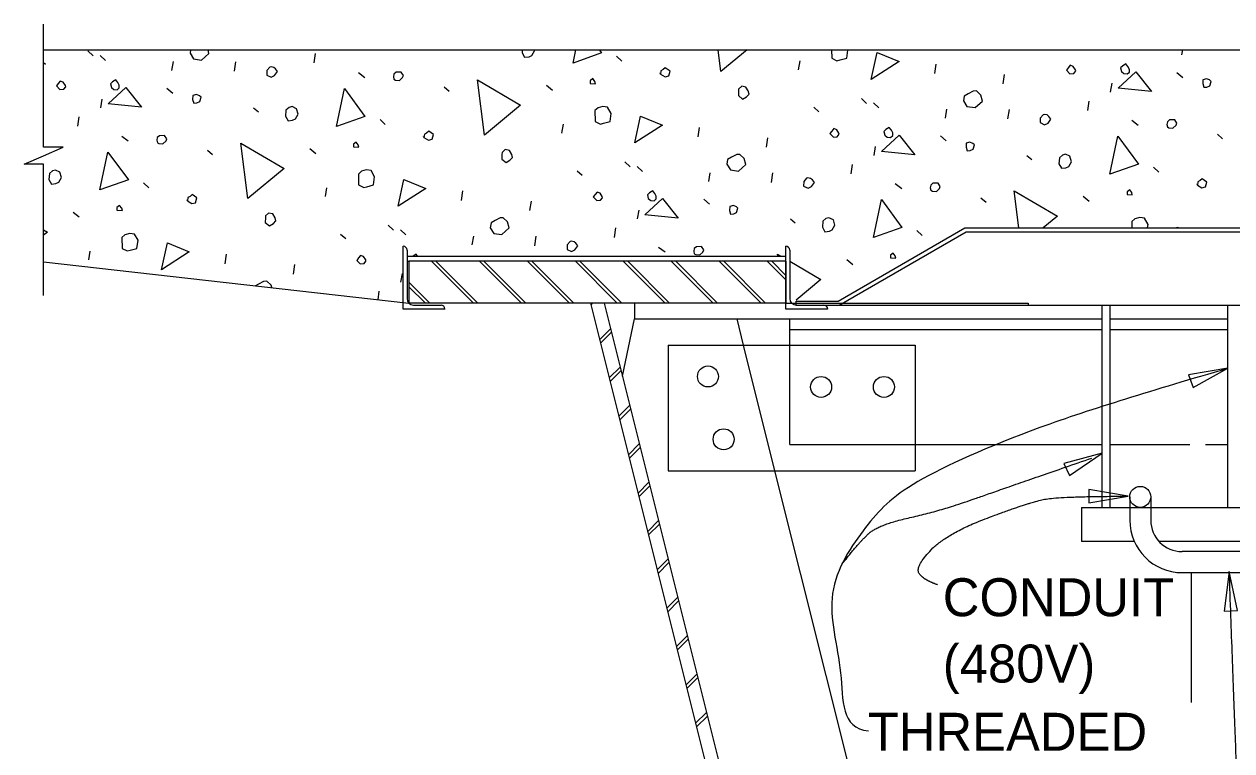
# Model space of a CAD drawing. Extents: x 927736.2 to 927809.6, y 636703.6 to 636757.7.
# Drawn here: x 927752.87 to 927764.73, y 636749.31 to 636756.45 of the extents above; entities that cross this region are included whole.
import ezdxf

# ---------------------------------------------------------------- set-up
doc = ezdxf.new("R2010")
doc.units = 0
for name, color, linetype in [('Default', 7, 'Continuous'), ('DimLines_dp', 7, 'Continuous'), ('Miscellaneous1', 7, 'Continuous'), ('Miscellaneous2', 7, 'Continuous'), ('Miscellaneous3', 7, 'Continuous')]:
    doc.layers.add(name, color=color, linetype=linetype)

msp = doc.modelspace()

# ---------------------------------------------------------------- linework, layer by layer
at = {"layer": 'Default'}
msp.add_line((927758.438, 636753.691), (927758.453, 636753.706), dxfattribs=at)
at = {"layer": 'DimLines_dp'}
msp.add_lwpolyline([(927753.063, 636753.782), (927753.063, 636755.07), (927752.871, 636755.07), (927753.063, 636755.153), (927753.254, 636755.237), (927753.063, 636755.237), (927753.063, 636756.446)], dxfattribs=at)
for points in [[(927764.692, 636753.067), (927764.306, 636753.003), (927764.349, 636752.88)], [(927763.458, 636752.234), (927763.081, 636752.133), (927763.135, 636752.014)], [(927763.711, 636751.811), (927763.325, 636751.876), (927763.325, 636751.746)], [(927764.705, 636751.071), (927764.654, 636750.684), (927764.785, 636750.688)]]:
    msp.add_lwpolyline(points, close=True, dxfattribs=at)
for points, degree in [([(927764.692, 636753.067), (927763.962, 636752.853), (927762.754, 636752.488), (927761.495, 636751.921), (927761.155, 636751.556), (927760.689, 636750.876), (927760.946, 636750.081), (927760.886, 636749.533), (927761.163, 636749.508)], 3), ([(927760.903, 636751.146), (927761.067, 636751.354), (927761.256, 636751.531), (927761.873, 636751.669), (927762.515, 636751.896), (927763.355, 636752.186)], 2), ([(927761.841, 636750.942), (927761.696, 636750.992), (927761.621, 636751.118), (927761.929, 636751.446), (927762.729, 636751.748), (927763.037, 636751.811), (927763.711, 636751.811)], 2), ([(927758.883, 636747.305), (927762.516, 636747.33), (927764.844, 636747.456), (927764.793, 636748.678), (927764.705, 636751.071)], 2)]:
    msp.add_open_spline(points, degree=degree, dxfattribs=at)
at = {"layer": 'Miscellaneous1'}
for p, q in [((927763.253, 636751.702), (927763.253, 636751.368)), ((927763.253, 636751.702), (927764.974, 636751.702)), ((927763.728, 636751.805), (927763.728, 636751.575)), ((927763.934, 636751.805), (927763.934, 636751.576)), ((927763.772, 636751.368), (927763.253, 636751.368)), ((927764.974, 636751.368), (927764.014, 636751.368)), ((927765.497, 636751.267), (927764.242, 636751.267)), ((927764.242, 636751.062), (927765.497, 636751.061))]:
    msp.add_line(p, q, dxfattribs=at)
msp.add_circle((927763.831, 636751.805), 0.103, dxfattribs=at)
for centre, radius in [((927764.242, 636751.575), 0.514), ((927764.242, 636751.576), 0.308)]:
    msp.add_arc(centre, radius, 180, 269.9792, dxfattribs=at)
at = {"layer": 'Miscellaneous2'}
for p, q in [((927753.063, 636756.193), (927774, 636756.193)), ((927753.498, 636756.185), (927753.55, 636756.135)), ((927753.618, 636756.14), (927753.67, 636756.09)), ((927755.72, 636756.065), (927755.733, 636756.158)), ((927758.689, 636756.133), (927758.741, 636756.083)), ((927760.475, 636755.998), (927760.49, 636756.085)), ((927764.24, 636756.145), (927764.248, 636756.193)), ((927753.063, 636756.069), (927753.08, 636756.053)), ((927754.322, 636755.991), (927754.337, 636756.078)), ((927754.937, 636755.983), (927754.951, 636756.076)), ((927756.154, 636755.971), (927756.217, 636755.924)), ((927761.813, 636755.961), (927761.826, 636756.054)), ((927764.191, 636755.973), (927764.249, 636755.924)), ((927758, 636755.846), (927758.058, 636755.798)), ((927762.485, 636755.86), (927762.498, 636755.953)), ((927763.54, 636755.779), (927763.555, 636755.866)), ((927754.273, 636755.818), (927754.331, 636755.769)), ((927756.995, 636755.832), (927757.045, 636755.788)), ((927753.623, 636755.624), (927753.638, 636755.711)), ((927755.123, 636755.624), (927755.171, 636755.586)), ((927760.625, 636755.63), (927760.675, 636755.586)), ((927761.093, 636755.717), (927761.144, 636755.667)), ((927761.213, 636755.673), (927761.265, 636755.623)), ((927761.917, 636755.523), (927761.932, 636755.61)), ((927762.532, 636755.515), (927762.546, 636755.608)), ((927763.315, 636755.597), (927763.328, 636755.69)), ((927753.397, 636755.443), (927753.41, 636755.535)), ((927756.366, 636755.51), (927756.418, 636755.46)), ((927763.749, 636755.503), (927763.812, 636755.456)), ((927758.152, 636755.376), (927758.167, 636755.463)), ((927759.49, 636755.339), (927759.503, 636755.432)), ((927753.831, 636755.348), (927753.894, 636755.301)), ((927760.161, 636755.238), (927760.175, 636755.331)), ((927761.868, 636755.35), (927761.925, 636755.302)), ((927764.59, 636755.365), (927764.64, 636755.321)), ((927754.672, 636755.21), (927754.722, 636755.166)), ((927755.677, 636755.224), (927755.735, 636755.175)), ((927761.217, 636755.157), (927761.232, 636755.244)), ((927762.718, 636755.157), (927762.766, 636755.118)), ((927758.77, 636755.095), (927758.821, 636755.045)), ((927758.89, 636755.05), (927758.942, 636755)), ((927760.992, 636754.975), (927761.005, 636755.068)), ((927763.961, 636755.043), (927764.013, 636754.993)), ((927758.302, 636755.007), (927758.352, 636754.963)), ((927759.594, 636754.901), (927759.609, 636754.988)), ((927760.209, 636754.893), (927760.223, 636754.986)), ((927754.043, 636754.888), (927754.095, 636754.838)), ((927755.829, 636754.753), (927755.844, 636754.84)), ((927757.167, 636754.716), (927757.18, 636754.809)), ((927761.425, 636754.881), (927761.489, 636754.834)), ((927757.838, 636754.615), (927757.852, 636754.708)), ((927759.545, 636754.728), (927759.602, 636754.679)), ((927762.267, 636754.742), (927762.317, 636754.698)), ((927763.272, 636754.756), (927763.33, 636754.708)), ((927753.354, 636754.601), (927753.412, 636754.553)), ((927758.894, 636754.534), (927758.909, 636754.621)), ((927756.447, 636754.472), (927756.498, 636754.422)), ((927756.567, 636754.428), (927756.619, 636754.378)), ((927758.669, 636754.352), (927758.682, 636754.445)), ((927760.395, 636754.534), (927760.443, 636754.496)), ((927760.864, 636753.726), (927762.11, 636754.446)), ((927761.638, 636754.42), (927761.69, 636754.37)), ((927762.11, 636754.446), (927774, 636754.446)), ((927755.978, 636754.385), (927756.029, 636754.341)), ((927757.271, 636754.278), (927757.286, 636754.365)), ((927757.886, 636754.27), (927757.899, 636754.363)), ((927760.874, 636753.688), (927762.121, 636754.407)), ((927762.121, 636754.407), (927774, 636754.407)), ((927753.506, 636754.131), (927753.521, 636754.218)), ((927754.844, 636754.094), (927754.857, 636754.187)), ((927756.593, 636753.649), (927756.593, 636754.266)), ((927756.631, 636754.227), (927756.631, 636753.752)), ((927759.102, 636754.258), (927759.166, 636754.211)), ((927760.35, 636753.649), (927760.35, 636754.266)), ((927760.389, 636754.227), (927760.389, 636753.752)), ((927753.063, 636754.114), (927756.65, 636753.706)), ((927755.515, 636753.993), (927755.529, 636754.086)), ((927756.631, 636754.169), (927760.35, 636754.169)), ((927756.631, 636754.118), (927756.65, 636754.118)), ((927757.283, 636753.706), (927756.872, 636754.118)), ((927757.326, 636753.706), (927756.915, 636754.118)), ((927757.754, 636753.706), (927757.343, 636754.118)), ((927757.797, 636753.706), (927757.386, 636754.118)), ((927758.225, 636753.706), (927757.813, 636754.118)), ((927758.268, 636753.706), (927757.857, 636754.118)), ((927758.696, 636753.706), (927758.284, 636754.118)), ((927758.739, 636753.706), (927758.328, 636754.118)), ((927759.167, 636753.706), (927758.755, 636754.118)), ((927759.21, 636753.706), (927758.799, 636754.118)), ((927759.638, 636753.706), (927759.226, 636754.118)), ((927759.681, 636753.706), (927759.27, 636754.118)), ((927760.108, 636753.706), (927759.697, 636754.118)), ((927760.152, 636753.706), (927759.741, 636754.118)), ((927760.35, 636753.936), (927760.168, 636754.118)), ((927760.35, 636753.979), (927760.212, 636754.118)), ((927760.35, 636754.118), (927760.35, 636753.706)), ((927760.949, 636754.134), (927761.007, 636754.085)), ((927756.571, 636753.912), (927756.586, 636753.999)), ((927756.856, 636753.706), (927756.65, 636753.912)), ((927756.812, 636753.706), (927756.65, 636753.868)), ((927756.347, 636753.741), (927756.359, 636753.823)), ((927760.344, 636753.706), (927760.35, 636753.713)), ((927760.344, 636753.706), (927760.35, 636753.713)), ((927760.453, 636753.726), (927760.864, 636753.726)), ((927760.453, 636753.688), (927760.453, 636753.726)), ((927757.004, 636753.649), (927756.593, 636753.649)), ((927756.695, 636753.688), (927756.965, 636753.688)), ((927760.761, 636753.649), (927760.35, 636753.649)), ((927760.453, 636753.688), (927760.723, 636753.688)), ((927760.453, 636753.688), (927774, 636753.688))]:
    msp.add_line(p, q, dxfattribs=at)
for points in [[(927754.501, 636756.16), (927754.534, 636756.105), (927754.614, 636756.094), (927754.686, 636756.158), (927754.677, 636756.193)], [(927754.505, 636756.193), (927754.501, 636756.16)], [(927757.763, 636756.193), (927757.761, 636756.165), (927757.786, 636756.121), (927757.829, 636756.126), (927757.858, 636756.14), (927757.884, 636756.185), (927757.882, 636756.193)], [(927758.261, 636756.063), (927758.289, 636756.193)], [(927758.519, 636756.193), (927758.541, 636756.163), (927758.261, 636756.063)], [(927759.714, 636755.98), (927759.687, 636756.193)], [(927759.972, 636756.193), (927759.714, 636755.98)], [(927760.799, 636756.193), (927760.802, 636756.112), (927760.853, 636756.087), (927760.883, 636756.095), (927760.949, 636756.113), (927760.959, 636756.192), (927760.959, 636756.193)], [(927761.19, 636755.903), (927761.247, 636756.167), (927761.462, 636756.078), (927761.19, 636755.903)], [(927755.254, 636755.991), (927755.254, 636755.946), (927755.297, 636755.926), (927755.331, 636755.942), (927755.359, 636755.981), (927755.339, 636756.008), (927755.323, 636756.022), (927755.296, 636756.028), (927755.284, 636756.025), (927755.254, 636755.991)], [(927756.503, 636755.905), (927756.518, 636755.896), (927756.557, 636755.894), (927756.588, 636755.921), (927756.595, 636755.942), (927756.574, 636755.975), (927756.523, 636755.974), (927756.503, 636755.955), (927756.497, 636755.928), (927756.503, 636755.905)], [(927759.12, 636755.955), (927759.166, 636755.928), (927759.201, 636755.938), (927759.214, 636755.986), (927759.167, 636756.018), (927759.146, 636756), (927759.124, 636755.988), (927759.12, 636755.955), (927759.117, 636755.967)], [(927763.106, 636755.995), (927763.141, 636755.959), (927763.178, 636755.963), (927763.197, 636755.987), (927763.194, 636755.999), (927763.173, 636756.032), (927763.144, 636756.043), (927763.125, 636756.019), (927763.106, 636755.995)], [(927763.613, 636755.818), (927763.787, 636755.979), (927763.941, 636755.784), (927763.613, 636755.818)], [(927763.646, 636755.98), (927763.671, 636755.961), (927763.703, 636755.957), (927763.724, 636755.975), (927763.724, 636756.001), (927763.71, 636756.029), (927763.69, 636756.055), (927763.657, 636756.034), (927763.637, 636756.016), (927763.646, 636755.98)], [(927753.188, 636755.84), (927753.223, 636755.805), (927753.26, 636755.808), (927753.28, 636755.832), (927753.276, 636755.844), (927753.255, 636755.877), (927753.226, 636755.888), (927753.207, 636755.864), (927753.188, 636755.84)], [(927753.728, 636755.825), (927753.753, 636755.806), (927753.786, 636755.802), (927753.806, 636755.82), (927753.806, 636755.846), (927753.792, 636755.874), (927753.772, 636755.901), (927753.739, 636755.879), (927753.719, 636755.861), (927753.728, 636755.825)], [(927757.391, 636755.357), (927757.322, 636755.9), (927757.746, 636755.65), (927757.391, 636755.357)], [(927758.429, 636755.865), (927758.482, 636755.86), (927758.475, 636755.884), (927758.455, 636755.911), (927758.429, 636755.891), (927758.429, 636755.865)], [(927764.444, 636755.862), (927764.454, 636755.826), (927764.485, 636755.828), (927764.513, 636755.842), (927764.527, 636755.884), (927764.511, 636755.899), (927764.482, 636755.91), (927764.446, 636755.901), (927764.444, 636755.862)], [(927753.695, 636755.663), (927753.869, 636755.824), (927754.023, 636755.63), (927753.695, 636755.663)], [(927754.526, 636755.707), (927754.536, 636755.671), (927754.567, 636755.673), (927754.595, 636755.687), (927754.61, 636755.729), (927754.593, 636755.744), (927754.564, 636755.755), (927754.529, 636755.746), (927754.526, 636755.707)], [(927755.938, 636755.44), (927756.017, 636755.813), (927756.218, 636755.541), (927755.938, 636755.44)], [(927759.886, 636755.79), (927759.885, 636755.745), (927759.926, 636755.711), (927759.965, 636755.734), (927759.99, 636755.76), (927759.982, 636755.79), (927759.959, 636755.828), (927759.918, 636755.836), (927759.887, 636755.809), (927759.886, 636755.79)], [(927762.095, 636755.692), (927762.129, 636755.637), (927762.209, 636755.627), (927762.281, 636755.691), (927762.265, 636755.75), (927762.222, 636755.79), (927762.191, 636755.788), (927762.141, 636755.762), (927762.102, 636755.739), (927762.095, 636755.692)], [(927755.442, 636755.601), (927755.438, 636755.543), (927755.463, 636755.498), (927755.506, 636755.503), (927755.535, 636755.517), (927755.561, 636755.563), (927755.546, 636755.616), (927755.503, 636755.637), (927755.473, 636755.629), (927755.442, 636755.601)], [(927758.476, 636755.597), (927758.479, 636755.489), (927758.53, 636755.465), (927758.56, 636755.473), (927758.625, 636755.49), (927758.636, 636755.57), (927758.601, 636755.63), (927758.554, 636755.637), (927758.507, 636755.624), (927758.476, 636755.597)], [(927758.867, 636755.28), (927758.924, 636755.544), (927759.139, 636755.455), (927758.867, 636755.28)], [(927762.849, 636755.524), (927762.848, 636755.479), (927762.892, 636755.459), (927762.926, 636755.474), (927762.954, 636755.514), (927762.934, 636755.54), (927762.917, 636755.555), (927762.89, 636755.56), (927762.879, 636755.557), (927762.849, 636755.524)], [(927764.098, 636755.437), (927764.113, 636755.428), (927764.152, 636755.426), (927764.183, 636755.453), (927764.19, 636755.475), (927764.169, 636755.507), (927764.118, 636755.506), (927764.097, 636755.488), (927764.092, 636755.461), (927764.098, 636755.437)], [(927756.797, 636755.332), (927756.843, 636755.306), (927756.878, 636755.316), (927756.891, 636755.364), (927756.844, 636755.396), (927756.823, 636755.377), (927756.801, 636755.365), (927756.797, 636755.332), (927756.794, 636755.344)], [(927760.783, 636755.372), (927760.818, 636755.337), (927760.855, 636755.341), (927760.874, 636755.365), (927760.871, 636755.377), (927760.85, 636755.409), (927760.821, 636755.421), (927760.802, 636755.397), (927760.783, 636755.372)], [(927761.323, 636755.357), (927761.347, 636755.338), (927761.38, 636755.334), (927761.401, 636755.353), (927761.401, 636755.378), (927761.387, 636755.406), (927761.367, 636755.433), (927761.334, 636755.411), (927761.314, 636755.393), (927761.323, 636755.357)], [(927754.18, 636755.282), (927754.195, 636755.273), (927754.234, 636755.271), (927754.265, 636755.299), (927754.272, 636755.32), (927754.251, 636755.352), (927754.2, 636755.351), (927754.179, 636755.333), (927754.174, 636755.306), (927754.18, 636755.282)], [(927755.068, 636754.735), (927754.999, 636755.278), (927755.423, 636755.028), (927755.068, 636754.735)], [(927756.106, 636755.243), (927756.159, 636755.238), (927756.152, 636755.261), (927756.132, 636755.288), (927756.106, 636755.268), (927756.106, 636755.243)], [(927761.29, 636755.195), (927761.464, 636755.357), (927761.618, 636755.162), (927761.29, 636755.195)], [(927762.121, 636755.239), (927762.131, 636755.204), (927762.162, 636755.206), (927762.19, 636755.219), (927762.204, 636755.262), (927762.188, 636755.276), (927762.159, 636755.288), (927762.123, 636755.278), (927762.121, 636755.239)], [(927763.533, 636754.973), (927763.612, 636755.345), (927763.813, 636755.073), (927763.533, 636754.973)], [(927753.615, 636754.818), (927753.694, 636755.19), (927753.895, 636754.918), (927753.615, 636754.818)], [(927757.563, 636755.167), (927757.562, 636755.122), (927757.603, 636755.088), (927757.642, 636755.112), (927757.667, 636755.137), (927757.659, 636755.167), (927757.636, 636755.206), (927757.595, 636755.214), (927757.564, 636755.187), (927757.563, 636755.167)], [(927759.772, 636755.07), (927759.806, 636755.015), (927759.886, 636755.004), (927759.958, 636755.068), (927759.942, 636755.128), (927759.899, 636755.167), (927759.868, 636755.165), (927759.818, 636755.139), (927759.779, 636755.116), (927759.772, 636755.07)], [(927763.037, 636755.133), (927763.033, 636755.075), (927763.058, 636755.031), (927763.101, 636755.036), (927763.129, 636755.05), (927763.156, 636755.095), (927763.141, 636755.149), (927763.097, 636755.169), (927763.068, 636755.161), (927763.037, 636755.133)], [(927753.119, 636754.979), (927753.115, 636754.92), (927753.14, 636754.876), (927753.183, 636754.881), (927753.212, 636754.895), (927753.238, 636754.94), (927753.223, 636754.994), (927753.18, 636755.014), (927753.15, 636755.006), (927753.119, 636754.979)], [(927756.153, 636754.974), (927756.156, 636754.867), (927756.207, 636754.842), (927756.237, 636754.85), (927756.302, 636754.868), (927756.313, 636754.947), (927756.278, 636755.008), (927756.231, 636755.015), (927756.183, 636755.002), (927756.153, 636754.974)], [(927756.544, 636754.658), (927756.601, 636754.922), (927756.816, 636754.833), (927756.544, 636754.658)], [(927760.526, 636754.901), (927760.525, 636754.856), (927760.569, 636754.836), (927760.603, 636754.852), (927760.631, 636754.891), (927760.611, 636754.918), (927760.594, 636754.932), (927760.567, 636754.938), (927760.555, 636754.935), (927760.526, 636754.901)], [(927764.392, 636754.865), (927764.437, 636754.838), (927764.473, 636754.848), (927764.486, 636754.896), (927764.439, 636754.928), (927764.418, 636754.91), (927764.396, 636754.898), (927764.392, 636754.865), (927764.389, 636754.877)], [(927758.46, 636754.75), (927758.495, 636754.715), (927758.532, 636754.718), (927758.551, 636754.742), (927758.548, 636754.754), (927758.527, 636754.787), (927758.498, 636754.798), (927758.479, 636754.774), (927758.46, 636754.75)], [(927759, 636754.735), (927759.024, 636754.716), (927759.057, 636754.712), (927759.078, 636754.73), (927759.078, 636754.756), (927759.064, 636754.784), (927759.044, 636754.811), (927759.011, 636754.789), (927758.991, 636754.771), (927759, 636754.735)], [(927761.775, 636754.815), (927761.79, 636754.806), (927761.829, 636754.804), (927761.86, 636754.831), (927761.867, 636754.852), (927761.846, 636754.885), (927761.795, 636754.884), (927761.774, 636754.865), (927761.769, 636754.838), (927761.775, 636754.815)], [(927762.64, 636754.446), (927762.593, 636754.81), (927763.018, 636754.56), (927762.879, 636754.446)], [(927763.701, 636754.775), (927763.753, 636754.77), (927763.747, 636754.794), (927763.727, 636754.821), (927763.701, 636754.801), (927763.701, 636754.775)], [(927753.783, 636754.62), (927753.836, 636754.615), (927753.829, 636754.639), (927753.809, 636754.666), (927753.783, 636754.646), (927753.783, 636754.62)], [(927754.474, 636754.71), (927754.519, 636754.684), (927754.555, 636754.693), (927754.568, 636754.741), (927754.521, 636754.773), (927754.5, 636754.755), (927754.478, 636754.743), (927754.474, 636754.71), (927754.471, 636754.722)], [(927758.967, 636754.573), (927759.141, 636754.734), (927759.295, 636754.54), (927758.967, 636754.573)], [(927759.798, 636754.617), (927759.808, 636754.581), (927759.839, 636754.583), (927759.867, 636754.597), (927759.881, 636754.639), (927759.865, 636754.654), (927759.836, 636754.665), (927759.8, 636754.656), (927759.798, 636754.617)], [(927761.21, 636754.35), (927761.289, 636754.723), (927761.49, 636754.451), (927761.21, 636754.35)], [(927755.24, 636754.545), (927755.239, 636754.5), (927755.28, 636754.466), (927755.319, 636754.489), (927755.344, 636754.515), (927755.336, 636754.545), (927755.312, 636754.583), (927755.272, 636754.592), (927755.241, 636754.564), (927755.24, 636754.545)], [(927757.449, 636754.447), (927757.483, 636754.392), (927757.563, 636754.382), (927757.635, 636754.446), (927757.619, 636754.505), (927757.576, 636754.545), (927757.545, 636754.543), (927757.495, 636754.517), (927757.456, 636754.494), (927757.449, 636754.447)], [(927760.714, 636754.511), (927760.71, 636754.453), (927760.735, 636754.408), (927760.778, 636754.413), (927760.806, 636754.427), (927760.833, 636754.473), (927760.818, 636754.526), (927760.774, 636754.546), (927760.745, 636754.538), (927760.714, 636754.511)], [(927763.903, 636754.446), (927763.908, 636754.479), (927763.872, 636754.54), (927763.826, 636754.547), (927763.778, 636754.534), (927763.747, 636754.507)], [(927753.063, 636754.427), (927753.1, 636754.405), (927753.063, 636754.374)], [(927763.747, 636754.507), (927763.749, 636754.446)], [(927764.194, 636754.446), (927764.195, 636754.454), (927764.216, 636754.446)], [(927753.829, 636754.352), (927753.833, 636754.244), (927753.884, 636754.22), (927753.914, 636754.228), (927753.979, 636754.245), (927753.99, 636754.325), (927753.955, 636754.385), (927753.908, 636754.392), (927753.86, 636754.379), (927753.829, 636754.352)], [(927758.203, 636754.279), (927758.202, 636754.234), (927758.246, 636754.214), (927758.28, 636754.229), (927758.308, 636754.269), (927758.288, 636754.295), (927758.271, 636754.31), (927758.244, 636754.315), (927758.232, 636754.312), (927758.203, 636754.279)], [(927754.221, 636754.035), (927754.278, 636754.3), (927754.493, 636754.21), (927754.221, 636754.035)], [(927756.735, 636754.169), (927756.721, 636754.188), (927756.692, 636754.169)], [(927759.452, 636754.192), (927759.467, 636754.183), (927759.506, 636754.181), (927759.537, 636754.209), (927759.544, 636754.23), (927759.523, 636754.262), (927759.472, 636754.261), (927759.451, 636754.243), (927759.446, 636754.216), (927759.452, 636754.192)], [(927760.273, 636754.169), (927760.27, 636754.188), (927760.303, 636754.169)], [(927761.378, 636754.153), (927761.43, 636754.148), (927761.424, 636754.171), (927761.404, 636754.198), (927761.377, 636754.178), (927761.378, 636754.153)], [(927756.137, 636754.127), (927756.172, 636754.092), (927756.209, 636754.096), (927756.228, 636754.12), (927756.225, 636754.132), (927756.204, 636754.164), (927756.175, 636754.176), (927756.156, 636754.152), (927756.137, 636754.127)], [(927760.389, 636754.118), (927760.695, 636753.938), (927760.451, 636753.736)], [(927755.302, 636753.86), (927755.296, 636753.883), (927755.253, 636753.923), (927755.222, 636753.921), (927755.171, 636753.894), (927755.144, 636753.878)]]:
    msp.add_lwpolyline(points, dxfattribs=at)
for centre, radius, start, end in [((927756.593, 636754.227), 0.0385, 359.9953, 89.9953), ((927760.35, 636754.227), 0.0385, 359.9953, 89.9953), ((927756.695, 636753.752), 0.0642, 179.9953, 269.9953), ((927760.453, 636753.752), 0.0642, 179.9953, 269.9953), ((927756.965, 636753.649), 0.0385, 359.9953, 89.9953), ((927760.723, 636753.649), 0.0385, 359.9953, 89.9953)]:
    msp.add_arc(centre, radius, start, end, dxfattribs=at)
at = {"layer": 'Miscellaneous3'}
for p, q in [((927760.35, 636754.118), (927756.65, 636754.118)), ((927756.65, 636754.118), (927756.65, 636753.706)), ((927760.35, 636753.706), (927756.65, 636753.706)), ((927758.434, 636753.706), (927762.288, 636738.29)), ((927758.566, 636753.706), (927762.42, 636738.29)), ((927758.867, 636753.552), (927758.867, 636753.706)), ((927760.35, 636753.706), (927762.729, 636753.706)), ((927762.729, 636753.706), (927762.729, 636753.688)), ((927763.458, 636751.702), (927763.458, 636753.688)), ((927763.535, 636751.702), (927763.535, 636753.688)), ((927764.692, 636751.702), (927764.692, 636753.688)), ((927758.862, 636753.552), (927758.745, 636752.99)), ((927758.867, 636753.552), (927763.458, 636753.552)), ((927759.868, 636753.552), (927759.933, 636753.295)), ((927760.389, 636753.269), (927760.389, 636753.552)), ((927763.535, 636753.552), (927764.692, 636753.552)), ((927758.523, 636753.349), (927758.629, 636753.455)), ((927758.532, 636753.315), (927758.638, 636753.421)), ((927760.389, 636752.319), (927760.389, 636753.449)), ((927760.389, 636753.449), (927763.458, 636753.449)), ((927763.535, 636753.449), (927764.692, 636753.449)), ((927759.194, 636753.295), (927759.194, 636752.062)), ((927759.194, 636753.295), (927761.622, 636753.295)), ((927759.933, 636753.295), (927760.241, 636752.062)), ((927761.622, 636753.295), (927761.622, 636752.062)), ((927758.617, 636752.973), (927758.723, 636753.079)), ((927758.626, 636752.938), (927758.732, 636753.044)), ((927758.711, 636752.596), (927758.817, 636752.702)), ((927758.72, 636752.561), (927758.826, 636752.667)), ((927758.806, 636752.219), (927758.912, 636752.325)), ((927758.814, 636752.184), (927758.92, 636752.29)), ((927760.389, 636752.319), (927761.622, 636752.319)), ((927761.622, 636752.319), (927763.458, 636752.319)), ((927763.535, 636752.319), (927764.319, 636752.319)), ((927764.473, 636752.319), (927764.692, 636752.319)), ((927759.194, 636752.062), (927761.622, 636752.062)), ((927760.241, 636752.062), (927762.676, 636742.324)), ((927758.9, 636751.842), (927759.006, 636751.948)), ((927758.909, 636751.808), (927759.015, 636751.914)), ((927758.994, 636751.466), (927759.1, 636751.572)), ((927759.003, 636751.431), (927759.109, 636751.537)), ((927759.088, 636751.089), (927759.194, 636751.195)), ((927759.097, 636751.054), (927759.203, 636751.16)), ((927759.182, 636750.712), (927759.288, 636750.818)), ((927759.191, 636750.677), (927759.297, 636750.783)), ((927759.277, 636750.335), (927759.383, 636750.441)), ((927759.285, 636750.301), (927759.391, 636750.407)), ((927759.371, 636749.959), (927759.477, 636750.065)), ((927759.379, 636749.924), (927759.485, 636750.03)), ((927759.465, 636749.582), (927759.571, 636749.688)), ((927759.474, 636749.547), (927759.58, 636749.653))]:
    msp.add_line(p, q, dxfattribs=at)
msp.add_lwpolyline([(927764.332, 636751.062), (927764.332, 636749.785)], dxfattribs=at)
for centre in [(927759.586, 636752.987), (927760.697, 636752.884), (927761.314, 636752.884), (927759.74, 636752.37)]:
    msp.add_circle(centre, 0.103, dxfattribs=at)

# ---------------------------------------------------------------- texts
at = {"layer": 'DimLines_dp'}
for s, p in [('CONDUIT', (927761.892, 636750.633)), ('(480V)', (927761.892, 636749.982)), ('THREADED', (927761.155, 636749.312))]:
    msp.add_text(s, height=0.373, dxfattribs=at).set_placement(p)

doc.saveas('drawing.dxf')
